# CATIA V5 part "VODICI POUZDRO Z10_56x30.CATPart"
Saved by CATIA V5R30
Part number: VODICI POUZDRO Z10/56x30
Bounding box of the stored display mesh (mm): x -9 to 56, y -23.5 to 23.5, z -23.5 to 23.5
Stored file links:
  C:\Users\ondra\Desktop\PŘÍLOHA P III\CATIA\VODICI POUZDRO Z10_56x30.CATPart
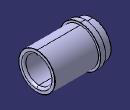
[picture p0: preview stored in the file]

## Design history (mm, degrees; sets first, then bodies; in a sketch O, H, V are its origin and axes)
Set1
  DatumSurface1 to DatumSurface24 "Z10/56x3"
  Join1: Elements (DatumSurface1; DatumSurface2; DatumSurface3; DatumSurface4; DatumSurface5; DatumSurface6; DatumSurface7; DatumSurface8; DatumSurface9; DatumSurface10; DatumSurface11; DatumSurface12; DatumSurface13; DatumSurface14; DatumSurface15; DatumSurface16; DatumSurface17; DatumSurface18; DatumSurface19; DatumSurface20; DatumSurface21; DatumSurface22; DatumSurface23; DatumSurface24)
Body1 (main body)
  CloseSurface1: CloseElement Join1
